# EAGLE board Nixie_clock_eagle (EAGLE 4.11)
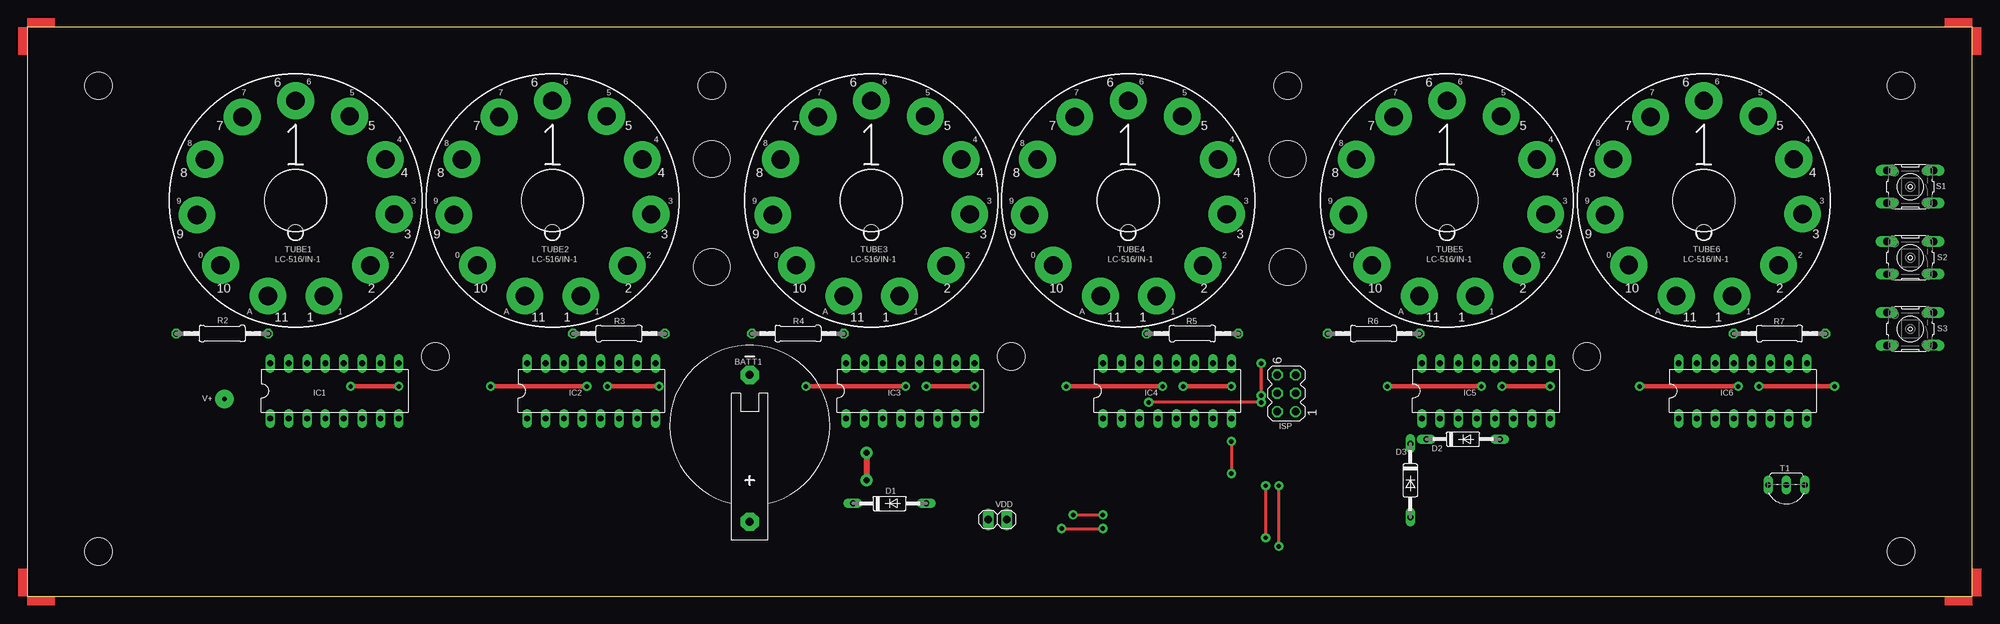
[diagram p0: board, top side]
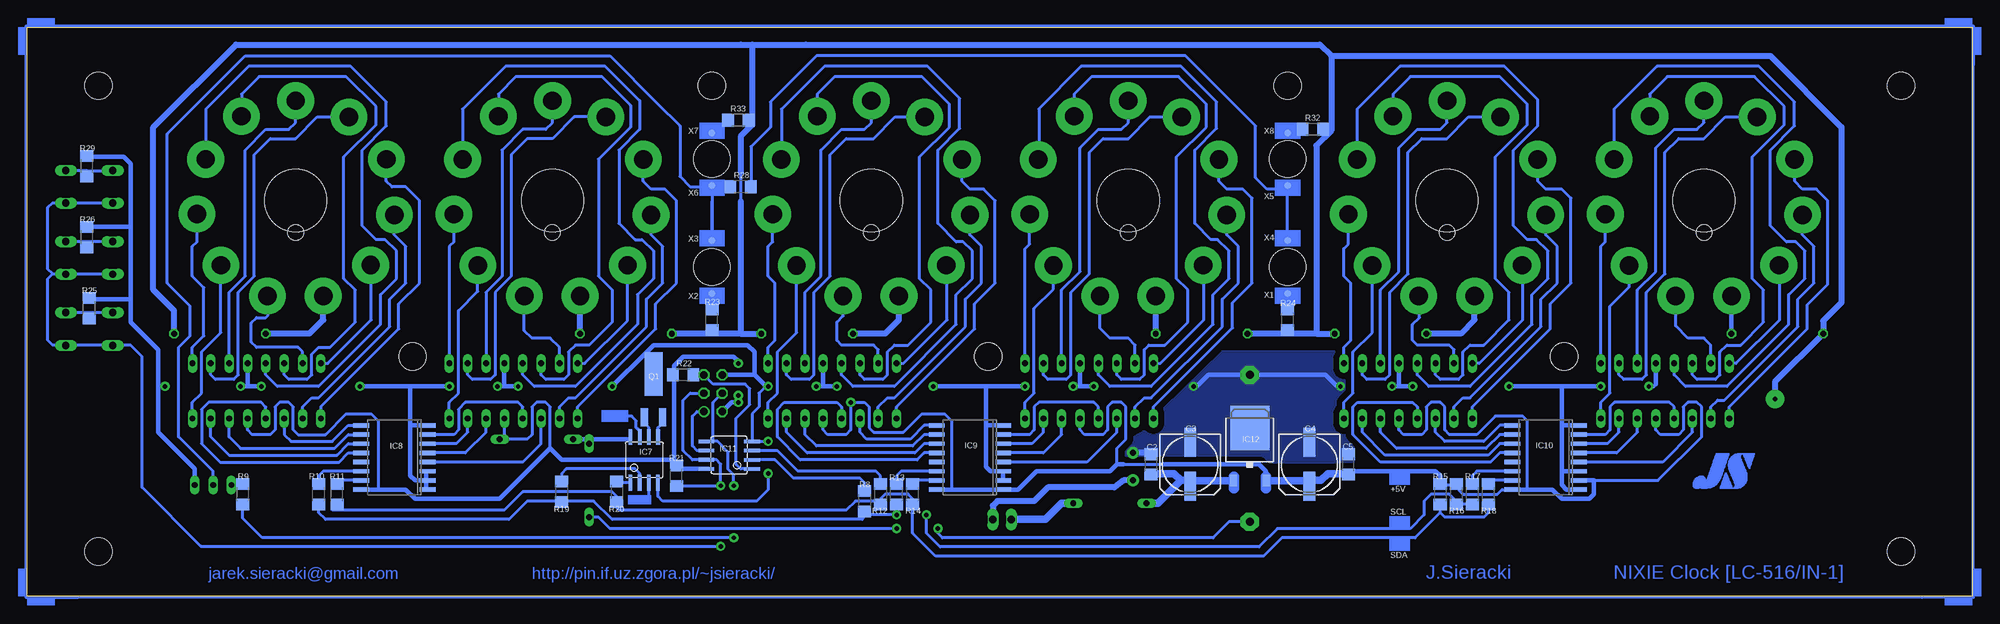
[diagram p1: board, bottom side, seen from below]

Size 269.22 x 78.73 mm. Coordinates in mm from the lower left corner, seen from the top.
Outline: 0,0 269.22,0 269.22,78.73 0,78.73 0,0
Copper layers (1*16): Top 0.035mm / dielectric 1.5mm / Bottom 0.035mm
Design rules "default": minimum track width 10mil, minimum drill 24mil, track to track 8mil, track to pad 8mil, pad to pad 8mil, via to via 8mil, smd to smd 8mil, copper to edge 40mil, drill to drill 8mil, minimum pad ring 10mil, minimum via ring 8mil, stop-mask expansion 4mil, vias tented up to drill 0mil, thermal gap 10mil
Holes 8.64 mm at 232.09,54.76 196.53,54.76 152.4,54.76 116.84,54.76 72.7,54.76 37.15,54.76
Holes 3.81 mm at 9.84,70.64 259.39,70.64 9.84,6.19 259.39,6.19 94.77,70.64 174.46,70.64 56.51,33.17 136.21,33.17 215.9,33.17
Holes 5.08 mm at 94.77,45.55 174.46,45.55 94.77,60.48 174.46,60.48
Holes 2.18 mm at 37.15,50.32 72.7,50.32 116.84,50.32 152.4,50.32 196.53,50.32 232.09,50.32

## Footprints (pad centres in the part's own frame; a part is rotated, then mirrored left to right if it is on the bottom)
BATTERY_PACK = drill 1.118 pad 2.54 octagon: + 0,12.7; - 0,-7.62
C1206 = smd 1.6 x 1.8: 1 -1.4,0; 2 1.4,0
153CLV-0807 = smd 4 x 1.6: + 3.05,0; - -3.05,0
DO35-10 = drill 0.813 long: A 5.08,0; C -5.08,0
DIL16 = drill 0.813 long: 1 -8.89,-3.81; 2 -6.35,-3.81; 3 -3.81,-3.81; 4 -1.27,-3.81; 5 1.27,-3.81; 6 3.81,-3.81; 7 6.35,-3.81; 8 8.89,-3.81; 9 8.89,3.81; 10 6.35,3.81; 11 3.81,3.81; 12 1.27,3.81; 13 -1.27,3.81; 14 -3.81,3.81; 15 -6.35,3.81; 16 -8.89,3.81
SOIC08 = smd 0.5 x 2.2: 1 -1.905,-3.154; 2 -0.645,-3.154; 3 0.625,-3.154; 4 1.895,-3.154; 5 1.905,3.154; 6 0.635,3.154; 7 -0.635,3.154; 8 -1.905,3.154
SO16W = smd 0.6 x 2.2: 1 -4.445,-4.6; 2 -3.175,-4.6; 3 -1.905,-4.6; 4 -0.635,-4.6; 5 0.635,-4.6; 6 1.905,-4.6; 7 3.175,-4.6; 8 4.445,-4.6; 9 4.445,4.6; 10 3.175,4.6; 11 1.905,4.6; 12 0.635,4.6; 13 -0.635,4.6; 14 -1.905,4.6; 15 -3.175,4.6; 16 -4.445,4.6
SOIC8 = smd 0.5 x 2.2: 1 -1.905,-3.154; 2 -0.645,-3.154; 3 0.625,-3.154; 4 1.895,-3.154; 5 1.905,3.154; 6 0.635,3.154; 7 -0.635,3.154; 8 -1.905,3.154
TO252 = smd 1 x 1.6: 1 -2.28,-4.8; 2 2.28,-4.8 | smd 5.4 x 6.2: 3 0,2.5
MA03-2 = drill 1.016 round: 1 -2.54,-1.27 | drill 1.016 octagon: 2 -2.54,1.27; 3 0,-1.27; 4 0,1.27; 5 2.54,-1.27; 6 2.54,1.27
QCYLSMD = smd 2.5 x 1: 1 3,-1.27; 2 3,1.27 | smd 6 x 2.5: 3 -3,0
0207/12 = drill 0.813 octagon: 1 -6.35,0; 2 6.35,0
R1206 = smd 1.6 x 1.803: 1 -1.422,0; 2 1.422,0
B3F-10XX = drill 1.016 long: 1 -3.251,2.261; 2 3.251,2.261; 3 -3.251,-2.261; 4 3.251,-2.261
TO92-BCE = drill 0.813 long: B 2.54,0; C 0,0; E -2.54,0
NIXIE_12 = drill 2.54 pad 5.08 round: 1 3.91,-13.23; 2 10.35,-8.98; 3 13.65,-1.89; 4 12.45,5.69; 5 7.49,11.66; 6 0,13.8; 7 -7.38,11.56; 8 -12.55,5.7; 9 -13.65,-2; 10 -10.38,-8.96; 11 -3.82,-13.22
1X02 = drill 1.016 long: 1 -1.27,0; 2 1.27,0
SMD-ELLIPSE = smd 1 x 1: 1 0,0

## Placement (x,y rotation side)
BATT1  3.6V  [BATTERY_PACK]  100.01,23.01 180 top
C2  100nF  [C1206]  113.66,18.25 90 bottom
C3  100uF/25V  [153CLV-0807]  108.27,18.25 270 bottom
C4  470uF/10V  [153CLV-0807]  91.75,18.25 270 bottom
C5  100nF  [C1206]  86.36,18.25 90 bottom
D1  1N4446  [DO35-10]  119.38,12.85 0 top
D2  BAT42  [DO35-10]  198.75,21.74 0 top
D3  BAT42  [DO35-10]  191.45,16.03 270 top
E$1  [ANGLE-SE1-16]  0,-0.01 0 top
E$2  [ANGLE-SE1-16]  0,78.74 270 top
E$3  [ANGLE-SE1-16]  269.25,78.74 180 top
E$4  [ANGLE-SE1-16]  269.25,-0.01 90 top
IC1  SN74141  [DIL16]  42.54,28.41 0 top
IC2  SN74141  [DIL16]  78.1,28.41 0 top
IC3  SN74141  [DIL16]  122.23,28.41 0 top
IC4  SN74141  [DIL16]  157.79,28.41 0 top
IC5  SN74141  [DIL16]  201.93,28.41 0 top
IC6  SN74141  [DIL16]  237.49,28.41 0 top
IC7  DS1629  [SOIC08]  183.83,18.89 0 bottom
IC8  PCF8574T  [SO16W]  218.44,19.2 90 bottom
IC9  PCF8574T  [SO16W]  138.74,19.2 90 bottom
IC10  PCF8574T  [SO16W]  59.05,19.2 90 bottom
IC11  ATtiny25  [SOIC8]  172.08,19.52 90 bottom
IC12  7805DT  [TO252]  100.01,20.79 0 bottom
ISP  [MA03-2]  174.31,28.09 90 top
Q1  32768Hz  [QCYLSMD]  182.56,27.77 270 bottom
R2  15k  [0207/12]  26.98,36.35 180 top
R3  15k  [0207/12]  81.91,36.35 0 top
R4  15k  [0207/12]  106.68,36.35 180 top
R5  15k  [0207/12]  161.29,36.35 0 top
R6  15k  [0207/12]  186.37,36.35 180 top
R7  15k  [0207/12]  242.57,36.35 0 top
R8  100  [R1206]  153.35,13.17 90 bottom
R9  10k  [R1206]  239.39,14.12 270 bottom
R10  100  [R1206]  228.91,14.12 270 bottom
R11  100  [R1206]  226.37,14.12 270 bottom
R12  100  [R1206]  151.13,14.12 90 bottom
R13  100  [R1206]  148.9,14.12 270 bottom
R14  100  [R1206]  146.68,14.12 270 bottom
R15  4.7k  [R1206]  73.66,14.12 90 bottom
R16  4.7k  [R1206]  71.44,14.12 90 bottom
R17  100  [R1206]  69.21,14.12 270 bottom
R18  100  [R1206]  66.99,14.12 270 bottom
R19  100  [R1206]  195.26,14.44 90 bottom
R20  100  [R1206]  187.64,14.44 90 bottom
R21  10k  [R1206]  179.38,16.66 270 bottom
R22  10k  [R1206]  178.43,30.63 0 bottom
R23  62k  [R1206]  174.46,38.25 270 bottom
R24  62k  [R1206]  94.77,38.25 270 bottom
R25  10k  [R1206]  260.67,39.84 270 bottom
R26  20k  [R1206]  260.98,49.68 270 bottom
R28  0  [R1206]  170.5,56.67 0 bottom
R29  40k  [R1206]  260.98,59.52 270 bottom
R32  62k  [R1206]  91.28,64.6 0 bottom
R33  62k  [R1206]  170.81,65.88 0 bottom
S1  [B3F-10XX]  260.67,56.67 180 top
S2  [B3F-10XX]  260.67,46.83 180 top
S3  [B3F-10XX]  260.67,36.98 180 top
T1  BF422  [TO92-BCE]  243.52,15.39 180 top
TUBE1  LC-516/IN-1  [NIXIE_12]  37.15,54.76 0 top
TUBE2  LC-516/IN-1  [NIXIE_12]  72.7,54.76 0 top
TUBE3  LC-516/IN-1  [NIXIE_12]  116.84,54.76 0 top
TUBE4  LC-516/IN-1  [NIXIE_12]  152.4,54.76 0 top
TUBE5  LC-516/IN-1  [NIXIE_12]  196.53,54.76 0 top
TUBE6  LC-516/IN-1  [NIXIE_12]  232.09,54.78 0 top
VDD  [1X02]  134.3,10.63 180 top
X1  [SMD-ELLIPSE]  94.77,41.9 0 bottom
X2  [SMD-ELLIPSE]  174.46,41.9 0 bottom
X3  [SMD-ELLIPSE]  174.46,49.21 0 bottom
X4  [SMD-ELLIPSE]  94.77,49.21 0 bottom
X5  [SMD-ELLIPSE]  94.77,56.83 0 bottom
X6  [SMD-ELLIPSE]  174.46,56.83 0 bottom
X7  [SMD-ELLIPSE]  174.46,64.13 0 bottom
X8  [SMD-ELLIPSE]  94.77,64.13 0 bottom

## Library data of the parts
BATT1 = battery_mod
C2-C5 R2-R26 R28 R29 R32 R33 = rcl
D1-D3 = diode
E$1-E$4 = marks
IC1-IC6 = SN74141
IC7 = DS1629
IC8-IC10 = micro-philips
IC11 = atmel
IC12 = linear
ISP = con-lstb
Q1 = ads4
S1-S3 = switch-omron
T1 = transistor
TUBE1-TUBE6 = LC-516
VDD = pinhead
X1-X8 = special-pad

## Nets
+5V: C4.+ C5.1 D2.A IC1.5 IC2.5 IC3.5 IC4.5 IC5.5 IC6.5 IC8.16 IC9.1 IC9.16 IC10.2 IC10.16 IC11.8 IC12.2 ISP.2 R15.2 R16.2 R21.1 R22.1
GND: BATT1.- C2.2 C3.- C4.- C5.2 IC1.12 IC2.12 IC3.12 IC4.12 IC5.12 IC6.12 IC7.4 IC8.1 IC8.2 IC8.3 IC8.8 IC9.2 IC9.3 IC9.8 IC10.1 IC10.3 IC10.8 IC11.4 IC12.3 ISP.6 Q1.3 R25.1 R26.1 R29.1 T1.E VDD.1
MISO: IC11.6 ISP.1
MOSI: IC11.5 ISP.4 R9.2
N$1: IC5.3 IC8.4
N$2: IC5.6 IC8.5
N$3: IC5.7 IC8.6
N$4: IC5.4 IC8.7
N$5: IC6.3 IC8.9
N$6: IC6.6 IC8.10
N$7: IC6.7 IC8.11
N$8: IC6.4 IC8.12
N$9: IC3.3 IC9.4
N$10: IC3.6 IC9.5
N$11: IC3.7 IC9.6
N$12: IC3.4 IC9.7
N$13: IC4.3 IC9.9
N$14: IC4.6 IC9.10
N$15: IC4.7 IC9.11
N$16: IC4.4 IC9.12
N$17: IC1.3 IC10.4
N$18: IC1.6 IC10.5
N$19: IC1.7 IC10.6
N$20: IC1.4 IC10.7
N$21: IC2.3 IC10.9
N$22: IC2.6 IC10.10
N$23: IC2.7 IC10.11
N$24: IC2.4 IC10.12
N$25: R11.2 R12.1 R14.2 R15.1 R18.2 R20.1
N$26: R8.1 R10.2 R13.2 R16.1 R17.2 R19.1
N$27: IC8.15 R11.1
N$28: IC8.14 R10.1
N$29: IC9.15 R14.1
N$30: IC9.14 R13.1
N$31: IC10.14 R17.1
N$32: IC10.15 R18.1
N$33: IC7.6 Q1.1
N$34: IC7.5 Q1.2
N$38: IC2.2 TUBE2.9
N$39: IC2.1 TUBE2.8
N$40: IC2.10 TUBE2.7
N$41: IC2.11 TUBE2.6
N$42: IC2.14 TUBE2.5
N$43: IC2.13 TUBE2.4
N$44: IC2.9 TUBE2.3
N$45: IC2.8 TUBE2.2
N$46: IC2.15 TUBE2.1
N$47: IC2.16 TUBE2.10
N$48: IC1.2 TUBE1.9
N$49: IC1.1 TUBE1.8
N$50: IC1.10 TUBE1.7
N$51: IC1.11 TUBE1.6
N$52: IC1.14 TUBE1.5
N$53: IC1.13 TUBE1.4
N$54: IC1.9 TUBE1.3
N$55: IC1.8 TUBE1.2
N$56: IC1.15 TUBE1.1
N$57: IC1.16 TUBE1.10
N$58: IC4.2 TUBE4.9
N$59: IC4.1 TUBE4.8
N$60: IC4.10 TUBE4.7
N$61: IC4.11 TUBE4.6
N$62: IC4.14 TUBE4.5
N$63: IC4.13 TUBE4.4
N$64: IC4.9 TUBE4.3
N$65: IC4.8 TUBE4.2
N$66: IC4.15 TUBE4.1
N$67: IC4.16 TUBE4.10
N$68: IC3.2 TUBE3.9
N$69: IC3.1 TUBE3.8
N$70: IC3.10 TUBE3.7
N$71: IC3.11 TUBE3.6
N$72: IC3.14 TUBE3.5
N$73: IC3.13 TUBE3.4
N$74: IC3.9 TUBE3.3
N$75: IC3.8 TUBE3.2
N$76: IC3.15 TUBE3.1
N$77: IC3.16 TUBE3.10
N$78: IC6.2 TUBE6.9
N$79: IC6.1 TUBE6.8
N$80: IC6.10 TUBE6.7
N$81: IC6.11 TUBE6.6
N$82: IC6.14 TUBE6.5
N$83: IC6.13 TUBE6.4
N$84: IC6.9 TUBE6.3
N$85: IC6.8 TUBE6.2
N$86: IC6.15 TUBE6.1
N$87: IC6.16 TUBE6.10
N$88: IC5.2 TUBE5.9
N$89: IC5.1 TUBE5.8
N$90: IC5.10 TUBE5.7
N$91: IC5.11 TUBE5.6
N$92: IC5.14 TUBE5.5
N$93: IC5.13 TUBE5.4
N$94: IC5.9 TUBE5.3
N$95: IC5.8 TUBE5.2
N$96: IC5.15 TUBE5.1
N$97: IC5.16 TUBE5.10
N$98: IC11.3 R12.2
N$99: R2.1 TUBE1.11
N$100: R3.1 TUBE2.11
N$101: R5.1 TUBE4.11
N$102: R4.1 TUBE3.11
N$103: R7.1 TUBE6.11
N$104: R6.1 TUBE5.11
N$105: IC11.2 R8.2
N$106: IC7.1 R20.2
N$107: IC7.2 R19.2
N$109: D2.C D3.C IC7.8
N$112: BATT1.+ D3.A
N$113: R25.2 S3.3 S3.4
N$114: C2.1 C3.+ D1.C IC12.1
N$115: R32.1 X8.1
N$116: R26.2 S2.3 S2.4
N$117: R29.2 S1.3 S1.4
N$118: R9.1 T1.B
N$119: R28.1 T1.C X3.1 X6.1
N$120: R28.2 X4.1 X5.1
N$121: R24.1 X1.1
N$122: R23.1 X2.1
N$124: R33.1 X7.1
RESET: IC11.1 ISP.5 R22.2
S$3: D1.A VDD.2
SCK: IC11.7 ISP.3 R21.2 S1.1 S1.2 S2.1 S2.2 S3.1 S3.2
V+: R2.2 R3.2 R4.2 R5.2 R6.2 R7.2 R23.2 R24.2 R32.2 R33.2

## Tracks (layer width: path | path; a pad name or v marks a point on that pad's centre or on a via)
+5V  (via drill 0.61 pad 1.27)
  Top 0.406: v170.81,32.22 v170.81,27.77 | v170.81,26.82 v155.25,26.82
  Bottom 0.406: IC5.5 203.19,22.37 202.56,21.74 D2.A 200.02,21.74 199.39,22.38 199.39,26.19 198.75,26.82 197.48,26.82 196.85,26.19 196.85,20.47 | IC6.5 238.75,23.01 238.12,22.38 235.58,22.38 234.95,23.01 234.95,26.19 234.31,26.82 233.04,26.82 232.41,26.19 232.41,23.01 231.77,22.38 227.96,22.38 225.1,25.23 221.61,25.23 220.66,24.28 220.66,14.76 | IC4.5 159.06,23.01 158.43,22.38 155.89,22.38 155.25,23.01 v155.25,26.82 153.35,26.82 152.72,26.19 152.72,23.33 152.08,22.69 147.95,22.69 145.41,25.23 142.24,25.23 141.28,24.28 141.28,14.76 | IC3.5 123.5,23.01 122.87,22.38 120.33,22.38 119.7,23.01 119.7,26.19 119.06,26.82 117.79,26.82 117.15,26.19 117.15,21.74 118.42,20.47 118.42,18.25 | IC1.5 43.81,23.01 43.18,22.38 40.64,22.38 40,23.01 40,26.19 39.37,26.82 38.1,26.82 37.46,26.19 37.46,22.06 43.5,16.03 52.39,16.03 | IC2.5 79.37,23.01 78.74,22.38 76.2,22.38 75.56,23.01 75.56,26.19 74.93,26.82 73.66,26.82 73.02,26.19 73.02,23.01 72.39,22.38 68.58,22.38 66.04,24.92 62.23,24.92 61.59,24.28 61.59,14.76 IC10.16 65.09,14.76 65.72,14.12 70.48,14.12 71.75,15.39 | 117.47,18.25 112.08,18.25 | R16.2 71.44,15.39 71.75,15.39 | 71.75,15.39 73.66,15.39 R15.2 73.66,15.71 | R22.1 179.85,31.12 179.7,31.27 | 97.79,16.5 97.75,15.99 IC12.2 | 91.75,16.03 91.79,15.99 91.79,15.11 91.75,15.07 C4.+ | 86.36,16.98 C5.1 86.49,16.85 86.36,16.98 | 86.36,16.98 86.04,17.3 | 179.7,18.25 R21.1
  Bottom 0.61: IC8.16 220.66,14.76 216.85,14.76 215.58,13.49 203.83,13.49 196.85,20.47 195.26,18.88 179.7,18.88 | IC9.16 141.28,14.76 IC9.1 132.08,14.76 129.54,17.3 119.38,17.3 118.42,18.25 117.47,18.25 | IC10.16 58.1,14.76 56.83,13.49 53.02,13.49 52.39,14.12 52.39,16.03 IC10.2 | 112.08,18.25 98.74,18.25 97.79,17.3 97.79,15.71 | 174.94,17.61 IC11.8 178.75,17.61 179.7,18.25 179.7,18.88 | ISP.2 171.77,26.82 v170.81,26.82 v170.81,27.77 | v170.81,32.22 170.81,32.54 171.45,33.17 178.43,33.17 179.7,31.9 179.7,31.27 179.7,18.88 | 86.04,17.3 74.29,17.3 73.66,16.66 73.66,15.71
  Bottom 1.016: IC12.2 91.79,15.99 | 91.75,16.03 90.17,16.03 89.22,16.98 86.36,16.98
  Bottom 1.422: 97.79,16.5 97.79,15.71 97.79,14.92
GND  (via drill 0.61 pad 1.27, 0.81 pad 1.68)
  Top 0.406: v166.69,21.42 v166.69,16.98
  Top 0.61: v210.82,29.04 v204.15,29.04 | v236.85,29.04 v223.2,29.04 | v166.69,29.04 v160.02,29.04 | v201.29,29.04 v188.28,29.04 | v157.16,29.04 v143.82,29.04 | v131.12,29.04 v124.46,29.04 | v121.6,29.04 v107.79,29.04 | v87.47,29.04 v80.33,29.04 | v77.47,29.04 v64.13,29.04 | v51.43,29.04 v44.76,29.04 | v250.19,29.04 v239.71,29.04
  Top 0.813: v116.2,19.84 v116.2,16.03
  Bottom 0.406: IC5.12 | v204.15,29.04 203.2,29.04 | 213.36,14.76 IC8.1 213.99,14.76 | 213.99,17.3 IC8.3 | 213.99,16.03 IC8.2 | IC6.12 238.75,29.04 | IC9.3 133.98,17.3 134.14,17.14 | 134.14,17.14 | 134.3,17.3 134.14,17.14 | 134.14,17.14 | IC3.12 123.5,29.04 123.5,29.05 | IC2.12 | IC1.12 | v44.76,29.04 44.13,29.04 | v166.69,29.04 167,29.04 167.96,28.09 167.96,26.19 168.91,25.23 168.91,21.42 | 260.98,60.79 R29.1 | 254.95,51.27 254.95,51.1 | 183.67,33.65 | Q1.3 182.56,32.54 183.67,33.65 | 113.66,19.52 C2.2 113.66,19.84 | IC7.4 181.95,13.83 181.29,13.17 168.27,13.17 166.69,14.76 v166.69,16.98 | 168.91,21.42 IC11.4 | 168.91,21.42 v166.69,21.42 | 260.67,41.11 R25.1
  Bottom 0.61: 203.2,29.04 IC5.12 | 216.22,29.04 v210.82,29.04 | 216.22,23.65 IC8.8 | 216.22,23.65 216.22,16.66 215.58,16.03 213.99,16.03 | 213.99,16.03 213.99,17.3 | 213.99,16.03 213.99,14.76 | 238.75,29.04 237.81,29.04 v236.85,29.04 | v223.2,29.04 216.22,29.04 | 134.14,17.14 IC9.2 | 136.52,23.65 136.52,17.93 135.89,17.3 134.3,17.3 | 216.22,29.04 216.22,23.65 | 159.06,29.04 IC4.12 | v160.02,29.04 159.06,29.04 | v188.28,29.04 183.67,33.65 182.56,34.76 169.54,34.76 168.59,33.81 168.59,30.63 | 168.59,30.63 167,29.04 | v204.15,29.04 v201.29,29.04 | 159.06,29.04 v157.16,29.04 | v143.82,29.04 136.52,29.04 | 136.52,29.04 v131.12,29.04 | v124.46,29.04 123.5,29.04 v121.6,29.04 | 136.52,23.65 IC9.8 | 136.52,29.04 136.52,23.65 | 123.5,29.05 IC3.12 | v107.79,29.04 107.31,29.04 105.73,30.63 BATT1.- 89.53,30.63 87.95,29.04 v87.47,29.04 | v80.33,29.04 79.37,29.04 | 79.37,29.04 IC2.12 | 79.37,29.04 v77.47,29.04 | v64.13,29.04 56.83,29.04 | 56.83,29.04 v51.43,29.04 | 44.13,29.04 43.81,29.36 IC1.12 | 56.83,23.65 56.83,17.3 | IC10.1 56.19,14.76 56.83,15.39 56.83,17.3 | 56.83,17.3 IC10.3 | 56.83,23.65 IC10.8 | 56.83,29.04 56.83,23.65 | 168.59,30.63 ISP.6 | 260.98,60.79 255.9,60.79 254.95,59.84 254.95,51.27 254.95,41.11 | 254.95,51.1 R26.1 | IC6.12 238.75,29.05 v239.71,29.04 | 251.14,29.04 v250.19,29.04 | 251.14,29.04 251.14,34.12 254.95,37.93 254.95,41.11 | 254.95,41.11 260.67,41.11 | T1.E 246.06,17.61 251.14,22.69 251.14,29.04
  Bottom 0.813: VDD.1 135.57,12.53 134.94,13.17 129.85,13.17 127.95,15.07 118.74,15.07 117.47,16.03 v116.2,16.03 | 113.66,19.84 v116.2,19.84
  pour Bottom (isolate 0.813, no thermals): 87.95,33.81 87.95,30.95 86.67,29.68 86.67,28.09 87.95,26.82 87.95,22.7 85.72,22.7 85.72,18.57 117.16,18.57 117.16,20.79 103.82,33.81
MISO
  Bottom 0.406: ISP.1 176.53,25.55 177.16,24.92 177.16,20.79 176.53,20.15 IC11.6
MOSI  (via drill 0.61 pad 1.27)
  Top 0.406: v171.45,8.09 v171.45,15.29
  Bottom 0.406: ISP.4 174.3,26.84 174.3,21.44 175.2,21.44 175.22,21.42 | 175.22,21.42 IC11.5 | 175.22,21.42 173.68,21.42 172.2,19.94 172.2,17.54 171.45,16.79 v171.45,15.29 | R9.2 239.39,10.79 236.7,8.09 v171.45,8.09
N$1
  Bottom 0.406: IC5.3 198.12,21.11 200.66,18.57 IC8.4
N$2
  Bottom 0.406: IC8.5 208.59,19.84 205.74,22.7 IC5.6
N$3
  Bottom 0.406: IC8.6 209.87,21.11 208.28,22.7 IC5.7
N$4
  Bottom 0.406: IC8.7 210.18,22.38 209.55,23.01 209.55,25.87 208.59,26.82 201.29,26.82 200.66,26.19 IC5.4
N$5
  Bottom 0.406: IC8.9 224.79,23.65 227.01,21.42 232.72,21.42 233.68,22.38 233.68,23.96 IC6.3
N$6
  Bottom 0.406: IC8.10 224.79,22.38 226.69,20.47 239.71,20.47 241.3,22.06 241.3,23.96 IC6.6
N$7
  Bottom 0.406: IC8.11 224.79,21.11 226.37,19.52 241.3,19.52 243.84,22.06 243.84,23.65 IC6.7
N$8
  Bottom 0.406: IC8.12 224.79,19.84 226.06,18.57 242.57,18.57 245.11,21.11 245.11,25.87 244.15,26.82 236.85,26.82 236.22,26.18 IC6.4
N$9
  Bottom 0.406: IC9.4 122.55,18.57 118.42,22.69 IC3.3
N$10
  Bottom 0.406: IC9.5 128.59,19.84 126.04,22.38 126.04,24.28 IC3.6
N$11
  Bottom 0.406: IC9.6 130.17,21.11 128.59,22.69 128.59,24.28 128.58,24.28 IC3.7
N$12
  Bottom 0.406: IC9.7 130.49,22.38 129.85,23.01 129.85,26.19 129.22,26.82 121.6,26.82 120.97,26.19 IC3.4
N$13
  Bottom 0.406: IC9.9 145.09,23.65 147,21.74 153.03,21.74 153.99,22.69 IC4.3
N$14
  Bottom 0.406: IC9.10 145.09,22.38 146.68,20.79 160.02,20.79 161.6,22.38 IC4.6
N$15
  Bottom 0.406: IC9.11 145.09,21.11 146.37,19.84 161.29,19.84 164.15,22.69 IC4.7
N$16
  Bottom 0.406: IC9.12 145.09,19.84 146.05,18.88 162.24,18.88 165.41,22.06 165.41,25.87 164.46,26.82 157.16,26.82 156.53,26.19 IC4.4
N$17
  Bottom 0.406: IC10.4 42.86,18.57 38.73,22.69 IC1.3
N$18
  Bottom 0.406: IC10.5 49.21,19.84 46.35,22.69 IC1.6
N$19
  Bottom 0.406: IC10.6 50.48,21.11 48.89,22.69 IC1.7
N$20
  Bottom 0.406: IC10.7 50.8,22.38 50.16,23.01 50.16,26.19 49.53,26.82 41.91,26.82 41.27,26.19 IC1.4
N$21
  Bottom 0.406: IC2.3 74.29,22.69 73.02,21.42 67.62,21.42 65.4,23.65 IC10.9
N$22
  Bottom 0.406: IC10.10 65.4,22.38 67.31,20.47 79.69,20.47 81.91,22.69 IC2.6
N$23
  Bottom 0.406: IC10.11 65.4,21.11 66.99,19.52 81.28,19.52 84.45,22.69 IC2.7
N$24
  Bottom 0.406: IC10.12 65.4,19.84 66.67,18.57 81.91,18.57 85.72,22.38 85.72,26.19 85.09,26.82 77.47,26.82 76.83,26.19 IC2.4
N$25
  Bottom 0.406: R11.2 226.37,12.54 227.01,11.9 203.2,11.9 200.66,14.44 188.28,14.44 187.64,13.8 187.64,13.17 | R18.2 66.99,11.58 67.62,10.95 73.02,10.95 73.66,11.58 73.66,12.53 73.66,12.54 R15.1 73.66,11.58 77.15,8.09 95.56,8.09 98.11,5.55 143.51,5.55 146.68,8.72 146.68,12.53 146.68,12.54 R14.2 146.68,13.48 147.32,14.12 150.49,14.12 151.13,13.49 151.13,13.17 | 187.64,13.17 R20.1 | 151.13,13.17 R12.1 | 151.13,13.17 154.62,13.17 155.89,11.9 187.32,11.9 187.64,12.22 187.64,13.17
N$26  (via drill 0.61 pad 1.27)
  Top 0.406: v144.78,11.26 v148.9,11.26
  Bottom 0.406: R13.2 148.9,11.9 v148.9,11.26 153.03,11.26 | 153.03,11.26 153.35,11.26 R8.1 | 153.03,11.26 153.67,10.63 188.28,10.63 190.81,13.17 195.58,13.17 | R10.2 228.91,12.54 228.91,12.53 228.91,11.58 227.96,10.63 202.56,10.63 200.02,13.17 195.58,13.17 | R17.2 69.21,12.85 69.36,12.7 R16.1 71.44,13.17 72.39,14.12 74.93,14.12 75.88,13.17 75.88,11.26 77.78,9.36 96.2,9.36 98.74,6.82 142.87,6.82 144.78,8.72 v144.78,11.26 | R19.1 195.26,13.17 195.58,13.17
N$27
  Bottom 0.406: R11.1 226.37,16.02 226.37,16.03 IC8.15
N$28
  Bottom 0.406: IC8.14 228.28,17.3 228.91,16.66 228.91,15.71 R10.1
N$29
  Bottom 0.406: R14.1 146.68,16.03 IC9.15
N$30
  Bottom 0.406: IC9.14 148.27,17.3 148.9,16.66 148.9,15.39 R13.1
N$31
  Bottom 0.406: IC10.14 68.58,17.3 69.21,16.66 69.21,15.71 R17.1
N$32
  Bottom 0.406: 66.67,16.03 | 66.67,16.03 R18.1 | 66.67,16.03 | IC10.15 66.67,16.03
N$33
  Bottom 0.406: IC7.6 183.19,23.33 183.83,23.96 Q1.1 183.83,24.92
N$34
  Bottom 0.406: IC7.5 181.93,23.33 181.29,23.96 Q1.2 181.29,24.92
N$38
  Bottom 0.406: TUBE2.9 59.05,50 57.47,48.41 57.47,43.33 59.69,41.11 59.69,37.3 69.53,27.46 70.48,27.46 71.75,26.19 IC2.2
N$39
  Bottom 0.406: TUBE2.8 60.15,57.45 59.05,56.35 56.83,56.35 55.56,55.08 55.56,43.33 58.42,40.47 58.42,36.98 69.21,26.19 IC2.1
N$40
  Bottom 0.406: TUBE2.7 69.72,66.32 72.7,63.33 76.2,63.33 78.1,61.43 78.1,44.6 80.64,42.06 80.64,30.63 81.28,30 83.82,30 84.45,30.63 84.45,31.9 IC2.10
N$41
  Bottom 0.406: TUBE2.6 72.7,65.56 73.66,64.6 76.83,64.6 79.37,62.06 79.37,44.92 81.91,42.38 81.91,32.54 IC2.11
N$42
  Bottom 0.406: TUBE2.5 80.2,69.5 77.78,71.91 65.4,71.91 61.59,68.1 61.59,65.24 66.04,60.79 66.04,43.97 64.13,42.06 64.13,38.25 67.62,34.76 69.53,34.76 70.48,33.81 70.48,30.63 71.12,30 73.66,30 74.29,30.63 IC2.14
N$43
  Bottom 0.406: TUBE2.4 85.15,67.39 79.21,73.34 64.77,73.34 60.16,68.73 60.16,65.08 63.5,61.75 63.5,51.27 61.59,49.36 60.32,49.36 58.73,47.78 58.73,43.97 60.96,41.74 60.96,37.62 69.53,29.04 75.25,29.04 76.83,30.63 IC2.13
N$44
  Bottom 0.406: IC2.9 86.99,34.44 86.04,35.39 86.04,43.33 86.99,44.28 86.99,48.1 86.36,48.73 86.36,52.54 TUBE2.3
N$45
  Bottom 0.406: TUBE2.2 83.06,36.47 85.72,33.81 85.72,28.09 86.99,26.82 IC2.8
N$46
  Bottom 0.406: IC2.15 71.75,34.12 72.39,34.76 76.83,34.76 77.47,35.39 77.47,37.62 76.51,38.57 76.51,41.43 TUBE2.1
N$47
  Bottom 0.406: IC2.16 68.26,32.22 62.23,38.25 62.23,45.55 62.33,45.65 TUBE2.10
N$48
  Bottom 0.406: TUBE1.9 23.49,50 21.9,48.41 21.9,43.33 24.13,41.11 24.13,37.3 34.29,27.14 35.24,27.14 36.19,26.19 36.19,24.92 36.19,24.91 IC1.2
N$49
  Bottom 0.406: TUBE1.8 24.6,57.45 23.49,56.35 21.59,56.35 20,54.76 20,43.17 22.86,40.32 22.86,36.98 33.65,26.19 IC1.1
N$50
  Bottom 0.406: TUBE1.7 34.16,66.32 37.15,63.33 40.64,63.33 42.54,61.43 42.54,44.6 45.08,42.06 45.08,30.63 45.72,30 48.26,30 48.89,30.63 IC1.10
N$51
  Bottom 0.406: TUBE1.6 37.15,65.56 38.1,64.6 41.27,64.6 43.81,62.06 43.81,44.92 46.35,42.38 IC1.11
N$52
  Bottom 0.406: TUBE1.5 44.64,69.5 42.22,71.91 30.16,71.91 26.03,67.78 26.03,65.24 30.48,60.79 30.48,43.97 28.89,42.38 28.89,37.93 32.07,34.76 33.97,34.76 34.92,33.81 34.92,30.63 35.56,30 38.1,30 38.73,30.63 IC1.14
N$53
  Bottom 0.406: TUBE1.4 49.59,67.39 43.65,73.34 29.52,73.34 24.6,68.41 24.6,65.08 27.94,61.75 27.94,51.27 25.72,49.05 24.45,49.05 23.17,47.78 23.17,43.97 25.4,41.74 25.4,37.62 33.97,29.04 39.69,29.04 41.27,30.63 41.27,31.9 IC1.13
N$54
  Bottom 0.406: IC1.9 51.43,48.41 50.8,49.05 50.8,52.54 50.79,52.54 TUBE1.3
N$55
  Bottom 0.406: TUBE1.2 47.5,42.82 50.16,40.16 50.16,28.09 51.43,26.82 IC1.8
N$56
  Bottom 0.406: TUBE1.1 41.05,37.4 39.37,35.71 37.15,35.71 36.19,34.76 36.19,32.54 36.19,32.53 IC1.15
N$57
  Bottom 0.406: IC1.16 32.7,32.22 26.67,38.25 26.67,45.55 26.76,45.65 TUBE1.10
N$58
  Bottom 0.406: TUBE4.9 138.75,50 137.16,48.41 137.16,43.33 139.38,41.11 139.38,37.3 149.22,27.46 150.18,27.46 151.44,26.19 IC4.2
N$59
  Bottom 0.406: TUBE4.8 139.85,57.45 138.75,56.35 136.84,56.35 135.25,54.76 135.25,43.33 138.11,40.47 138.11,36.98 148.9,26.19 IC4.1
N$60
  Bottom 0.406: TUBE4.7 149.09,66.32 152.08,63.33 155.89,63.33 158.11,61.11 158.11,44.28 160.34,42.06 160.34,30.63 160.97,30 163.51,30 164.15,30.63 IC4.10
N$61
  Bottom 0.406: TUBE4.6 152.4,65.56 153.35,64.6 156.53,64.6 159.38,61.75 159.38,44.28 161.6,42.06 IC4.11
N$62
  Bottom 0.406: TUBE4.5 159.89,69.5 157.48,71.91 145.41,71.91 141.6,68.1 141.6,64.92 145.73,60.79 145.73,43.97 144.14,42.38 144.14,37.93 147.32,34.76 149.22,34.76 150.18,33.81 150.18,30.63 150.81,30 153.35,30 153.99,30.63 IC4.14
N$63
  Bottom 0.406: TUBE4.4 164.85,67.39 158.91,73.34 144.62,73.34 140.17,68.89 140.17,64.76 143.19,61.75 143.19,51.59 140.65,49.05 139.7,49.05 138.43,47.78 138.43,43.97 140.65,41.74 140.65,37.62 149.22,29.04 154.94,29.04 156.53,30.63 156.53,31.9 156.52,31.9 IC4.13
N$64
  Bottom 0.406: IC4.9 166.68,34.44 165.73,35.39 165.73,43.33 166.69,44.28 166.68,48.41 166.05,49.05 166.05,53.17 TUBE4.3
N$65
  Bottom 0.406: TUBE4.2 162.75,36.47 165.41,33.81 165.41,28.09 166.69,26.82 166.69,24.92 166.68,24.91 IC4.8
N$66
  Bottom 0.406: IC4.15 151.44,32.53 151.44,32.54 151.44,34.12 152.08,34.76 156.53,34.76 157.16,35.39 157.16,37.93 156.31,38.79 TUBE4.1
N$67
  Bottom 0.406: IC4.16 147.95,32.22 141.92,38.25 141.92,45.87 141.99,45.8 TUBE4.10
N$68
  Bottom 0.406: TUBE3.9 103.19,50 101.6,48.41 101.6,43.33 103.82,41.11 103.82,37.3 113.66,27.46 114.62,27.46 115.89,26.19 115.89,24.92 115.88,24.91 IC3.2
N$69
  Bottom 0.406: TUBE3.8 104.29,57.45 103.19,56.35 100.96,56.35 99.69,55.08 99.69,43.33 102.39,40.63 102.39,37.14 113.34,26.19 IC3.1
N$70
  Bottom 0.406: TUBE3.7 113.85,66.32 116.84,63.33 120.33,63.33 122.23,61.43 122.23,44.6 124.78,42.06 124.78,30.63 125.41,30 127.95,30 128.59,30.63 IC3.10
N$71
  Bottom 0.406: TUBE3.6 116.84,65.56 117.79,64.6 120.97,64.6 123.5,62.06 123.5,44.92 126.04,42.38 IC3.11
N$72
  Bottom 0.406: TUBE3.5 124.33,69.5 121.92,71.91 109.85,71.91 106.04,68.1 106.04,64.92 110.17,60.79 110.17,43.97 108.58,42.38 108.58,37.93 111.76,34.76 113.98,34.76 114.62,34.12 114.62,30.63 115.25,30 117.79,30 118.42,30.63 118.42,31.9 IC3.14
N$73
  Bottom 0.406: IC3.13 120.97,30.63 119.38,29.04 113.66,29.04 105.09,37.62 105.09,41.74 102.87,43.97 102.87,47.78 104.45,49.36 105.41,49.36 107.63,51.59 107.63,61.75 104.61,64.76 104.61,68.41 109.54,73.34 123.35,73.34 129.22,67.46 129.22,60.45 TUBE3.4
N$74
  Bottom 0.406: IC3.9 131.12,48.1 130.49,48.73 130.49,52.86 TUBE3.3
N$75
  Bottom 0.406: TUBE3.2 127.19,42.51 129.85,39.84 129.85,28.09 131.12,26.82 131.12,24.92 131.12,24.91 IC3.8
N$76
  Bottom 0.406: TUBE3.1 120.75,37.08 119.38,35.71 116.84,35.71 115.89,34.76 115.89,32.54 115.88,32.53 IC3.15
N$77
  Bottom 0.406: IC3.16 112.39,32.22 106.36,38.25 106.36,45.87 106.43,45.8 TUBE3.10
N$78
  Bottom 0.406: TUBE6.9 218.44,50 216.85,48.41 216.85,43.33 219.07,41.11 219.07,37.3 228.91,27.46 229.87,27.46 231.14,26.19 231.14,24.28 231.13,24.28 IC6.2
N$79
  Bottom 0.406: TUBE6.8 219.54,57.45 218.75,56.67 216.85,56.67 214.94,54.76 214.94,43.33 217.8,40.47 217.8,36.98 228.6,26.19 228.6,23.65 228.59,23.65 IC6.1
N$80
  Bottom 0.406: TUBE6.7 229.09,66.33 232.09,63.33 235.58,63.33 237.81,61.11 237.81,44.28 240.03,42.06 240.03,30.63 240.66,30 243.2,30 243.84,30.63 243.84,31.58 IC6.10
N$81
  Bottom 0.406: TUBE6.6 232.09,65.56 233.04,64.6 236.22,64.6 239.07,61.75 239.07,44.28 241.3,42.06 241.3,31.58 IC6.11
N$82
  Bottom 0.406: TUBE6.5 239.58,69.5 237.17,71.91 225.1,71.91 220.98,67.78 220.98,65.24 225.42,60.79 225.42,43.97 223.84,42.38 223.84,37.93 227.33,34.44 228.91,34.44 229.87,33.49 229.87,30.63 230.5,30 233.04,30 233.68,30.63 233.68,31.27 IC6.14
N$83
  Bottom 0.406: TUBE6.4 244.54,67.39 238.6,73.34 224.47,73.34 219.55,68.41 219.55,65.08 222.88,61.75 222.88,51.27 220.98,49.36 219.71,49.36 218.12,47.78 218.12,43.97 220.34,41.74 220.34,37.62 228.91,29.04 234.63,29.04 236.22,30.63 236.22,31.27 IC6.13
N$84
  Bottom 0.406: TUBE6.3 245.74,49.05 246.38,48.41 246.38,44.28 244.79,42.7 244.79,36.03 246.38,34.44 IC6.9
N$85
  Bottom 0.406: TUBE6.2 242.44,36.47 245.11,33.81 245.11,28.09 246.38,26.82 246.38,23.96 IC6.8
N$86
  Bottom 0.406: IC6.15 231.13,31.9 231.14,31.9 231.14,33.81 231.77,34.44 237.49,34.44 238.22,35.18 238.22,37.83 237.49,38.57 236.22,38.57 235.9,38.89 235.9,41.43 236,41.53 TUBE6.1
N$87
  Bottom 0.406: IC6.16 227.65,32.22 221.61,38.25 221.61,45.87 221.67,45.81 TUBE6.10
N$88
  Bottom 0.406: IC5.2 195.57,26.19 194.31,27.46 193.35,27.46 183.51,37.3 183.51,41.11 181.29,43.33 181.29,48.41 182.88,50 TUBE5.9
N$89
  Bottom 0.406: IC5.1 193.04,26.19 182.24,36.98 182.24,40.47 179.38,43.33 179.38,54.76 180.97,56.35 182.88,56.35 183.98,57.45 TUBE5.8
N$90
  Bottom 0.406: TUBE5.7 193.54,66.32 196.53,63.33 200.02,63.33 202.25,61.11 202.25,44.28 204.47,42.06 204.47,30.63 205.1,30 207.64,30 208.28,30.63 IC5.10
N$91
  Bottom 0.406: TUBE5.6 196.53,65.56 197.48,64.6 200.66,64.6 203.52,61.75 203.52,44.28 205.74,42.06 IC5.11
N$92
  Bottom 0.406: TUBE5.5 204.02,69.5 201.61,71.91 189.7,71.91 185.74,67.94 185.74,64.92 190.18,60.48 190.18,44.28 188.28,42.38 188.28,37.93 191.45,34.76 193.35,34.76 194.31,33.81 194.31,30.63 194.94,30 197.48,30 198.12,30.63 IC5.14
N$93
  Bottom 0.406: TUBE5.4 208.98,67.39 203.04,73.34 189.23,73.34 184.47,68.57 184.47,64.6 187.32,61.75 187.32,51.59 185.1,49.36 184.15,49.36 182.56,47.78 182.56,43.97 184.78,41.74 184.78,37.62 193.35,29.04 199.07,29.04 200.66,30.63 200.66,31.9 200.65,31.9 IC5.13
N$94
  Bottom 0.406: TUBE5.3 210.18,49.05 210.82,48.41 IC5.9
N$95
  Bottom 0.406: TUBE5.2 206.88,42.19 209.55,39.52 209.55,28.09 210.82,26.82 210.82,24.92 210.81,24.91 IC5.8
N$96
  Bottom 0.406: IC5.15 195.57,32.53 195.58,32.54 195.58,34.44 196.85,35.71 199.39,35.71 200.44,36.76 TUBE5.1
N$97
  Bottom 0.406: TUBE5.10 186.15,38.15 192.09,32.22 IC5.16
N$98
  Bottom 0.406: IC11.3 168.6,20.14 168.59,20.15 165.41,20.15 162.56,17.3 151.76,17.3 151.13,16.66 R12.2
N$99
  Bottom 0.61: TUBE1.11 33.33,36.36 R2.1
N$100
  Bottom 0.813: TUBE2.11 68.89,38.26 70.8,36.35 R3.1
N$101
  Bottom 0.61: TUBE4.11 148.58,41.73 148.59,41.74
  Bottom 0.813: R5.1 150.49,36.35 148.59,38.25 148.59,41.74
N$102
  Bottom 0.61: R4.1 113.02,36.36
  Bottom 0.813: 113.02,36.36 TUBE3.11
N$103
  Bottom 0.61: TUBE6.11 228.27,41.44 228.28,41.43
  Bottom 0.813: R7.1 230.19,36.35 228.28,38.25 228.28,41.43
N$104
  Bottom 0.61: 192.72,41.43 192.71,41.44 TUBE5.11
  Bottom 0.813: R6.1 192.72,41.43
N$105
  Bottom 0.406: IC11.2 168.91,18.88 165.73,18.88 163.19,16.34 153.99,16.34 153.35,15.71 R8.2 153.35,14.44
N$106
  Bottom 0.406: IC7.1 187.62,15.73 187.64,15.71 R20.2
N$107
  Bottom 0.406: IC7.2 184.47,16.99 185.1,17.61 194.62,17.61 195.26,16.98 R19.2
N$109
  Bottom 0.406: IC7.8 185.89,21.74
  Bottom 0.61: 185.89,21.74 D2.C 191.45,21.74 D3.C
N$112  (via drill 0.61 pad 1.27)
  Top 0.406: v143.19,9.36 v148.9,9.36
  Bottom 0.406: BATT1.+ 102.87,10.31 105.09,8.09 142.56,8.09 143.19,8.72 v143.19,9.36 | v148.9,9.36 188.59,9.36 190.18,10.95 D3.A
N$113
  Bottom 0.406: S3.3 263.88,39.24 263.84,39.2 263.8,39.24 260.67,39.24 | S3.4 260.67,39.24 | 260.67,39.24 R25.2
N$114
  Bottom 0.406: 108.23,15.99 108.26,16.03 C3.+ | C2.1 113.48,16.85 113.03,16.98
  Bottom 1.016: 113.03,16.98 110.49,16.98 109.53,16.03 | 108.26,16.03 109.53,16.03 | D1.C 112.71,12.85 109.53,16.03 | IC12.1 108.23,15.99
  Bottom 1.422: 102.23,15.99 102.23,16.5 | 102.23,15.99 IC12.1 | 102.23,14.92 102.23,15.99
N$115
  Bottom 0.406: X8.1 | R32.1 94.3,64.6 X8.1
N$116
  Bottom 0.406: S2.4 257.41,49.05 260.98,49.05 | S2.3 263.92,49.05 260.98,49.05 | 260.98,49.05 R26.2
N$117
  Bottom 0.406: S1.3 263.92,58.89 260.98,58.89 | S1.4 257.41,58.89 260.98,58.89 | R29.2 260.98,58.89
N$118
  Bottom 0.406: 238.76,15.39 | R9.1 238.76,15.39 | 238.76,15.39 T1.B
N$119
  Bottom 0.406: T1.C 243.52,17.3 248.28,22.06 248.28,34.44 246.69,36.03 246.69,40.16 249.87,43.33 249.87,63.97 239.07,74.76 188.59,74.76 182.08,68.26 178.91,65.08 178.91,58.1 177.48,56.67 174.46,56.67 | X3.1 | 174.46,56.67 X3.1 | X3.1 174.46,54.6 | 173.51,56.67 R28.1 | 174.46,56.67 173.51,56.67 | 173.51,56.67 174.31,56.67 X6.1
N$120
  Bottom 0.406: X4.1 94.77,56.35 | R28.2 169.07,62.22 166.37,64.92 166.37,68.41 160.02,74.76 108.9,74.76 99.22,65.08 99.22,57.94 97.63,56.35 94.77,56.35 | 94.77,56.35 X5.1
N$121
  Bottom 0.406: X1.1
  Bottom 0.813: R24.1 X1.1
N$122
  Bottom 0.406: X2.1 | X2.1
  Bottom 0.813: R23.1 X2.1
N$123
  Bottom 0.406: -0.16,78.89 -0.16,73.49 | -0.16,-0.17 6.98,-0.17 | 262.41,-0.17 262.25,-0.17 | 262.41,-0.17 269.4,-0.17 | 269.4,-0.17 269.4,78.89 -0.16,78.89 | -0.16,-0.17 | -0.16,-0.17 -0.16,78.89 | 6.98,-0.17 269.4,-0.17 | 6.98,-0.17 | 269.4,-0.17 262.41,-0.17 | 262.41,-0.17
N$124
  Bottom 0.406: R33.1 172.4,65.87 173.19,65.08 174.31,65.08 174.46,64.92 X7.1 | X7.1
N$125
  Bottom 0.406: 184.47,22.54 184.47,22.85 184.78,23.17 | 184.78,23.17 | 184.78,23.17 184.94,23.33 184.94,24.28 185.58,24.92 186.21,24.92
N$126
  Bottom 0.406: 183.19,15.23 183.19,13.65 183.51,13.33 183.83,13.33
RESET
  Bottom 0.406: 168.91,17.61 IC11.1 170.5,17.61 171.13,18.25 171.13,24.6 169.22,26.5 169.22,28.73 169.86,29.36 174.31,29.36 ISP.5 R22.2
S$1  (via drill 0.61 pad 2.54)
  other vias: 27.3,27.29
S$2
  Bottom 0.406: 238.76,12.85 239.39,12.85
S$3
  Bottom 1.016: VDD.2 128.27,10.63 126.04,12.85 D1.A
SCK  (via drill 0.61 pad 1.27)
  Top 0.406: v173.25,6.89 v173.25,15.29
  Bottom 0.406: S1.2 257.41,54.44 263.92,54.44 S1.1 264.12,54.41 264.16,54.44 265.75,54.44 266.38,53.81 266.38,45.24 265.75,44.6 | S2.1 263.92,44.6 263.84,44.6 | ISP.3 177.48,28.09 178.43,27.14 178.43,20.15 177.16,18.88 IC11.7 | 257.41,44.6 S2.2 | 263.84,44.6 257.41,44.6 | 265.75,44.6 263.84,44.6 | 265.75,44.6 257.41,44.6 | 265.75,44.6 266.38,43.97 266.38,35.39 265.75,34.76 263.84,34.76 | IC11.7 175.21,18.88 175.2,18.89 | S3.1 263.92,34.76 263.84,34.76 | 263.84,34.76 257.41,34.76 S3.2 257.21,34.72 257.17,34.76 254.95,34.76 253.36,33.17 253.36,15.07 245.21,6.92 173.27,6.92 173.12,6.88 v173.25,6.89 | R21.2 173.3,15.24 v173.25,15.29 173.25,18.29 173.85,18.89 175.05,18.89 175.06,18.88 IC11.7
V+
  Bottom 0.406: 170.5,58.73 170.5,54.6 | 174.31,36.35 174.31,36.51 174.46,36.66 | 94.77,36.35 | 88.74,64.6 R32.2 | 168.91,65.87 R33.2 | 174.46,36.35 R23.2 | 174.46,36.35 | 18.17,40.55 18.1,41.67 | 18.1,40.79 17.94,40.63 | R24.2 | 94.77,36.35 R24.2 | 18.1,63.97 17.94,63.97 | 18.1,64.6 17.94,64.6
  Bottom 0.61: 18.1,63.97 18.09,63.97
  Bottom 0.813: 168.91,76.35 168.91,65.87 168.91,65.24 170.5,63.65 170.5,58.73 | 170.5,54.6 170.5,36.35 | 88.74,74.76 88.74,64.6 88.74,64.45 90.8,62.38 90.8,36.35 | R7.2 248.92,39.52 251.78,42.38 251.78,64.92 240.34,76.35 170.5,76.35 168.91,76.35 | 170.5,36.35 174.31,36.35 174.46,36.35 R6.2 | 170.5,36.35 R5.2 | 168.91,76.35 161.45,76.35 90.33,76.35 88.74,74.76 | 90.8,36.35 94.77,36.35 R4.2 | 90.8,36.35 R3.2 | 88.74,74.76 27.94,74.76 18.1,64.92 18.1,64.6 18.1,63.97 18.1,40.63 18.17,40.55 20.63,38.09 R2.2 27.3,29.68 27.3,28.25 27.3,27.34 | 18.1,41.67 18.1,40.79
(copper drawn outside any net)
  shapes: Bottom area x326

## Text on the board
Bottom: NIXIE Clock [LC-516/IN-1] | J.Sieracki | http://pin.if.uz.zgora.pl/~jsieracki/ | jarek.sieracki@gmail.com
tPlace: V+
bPlace: +5V | SCL | SDA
